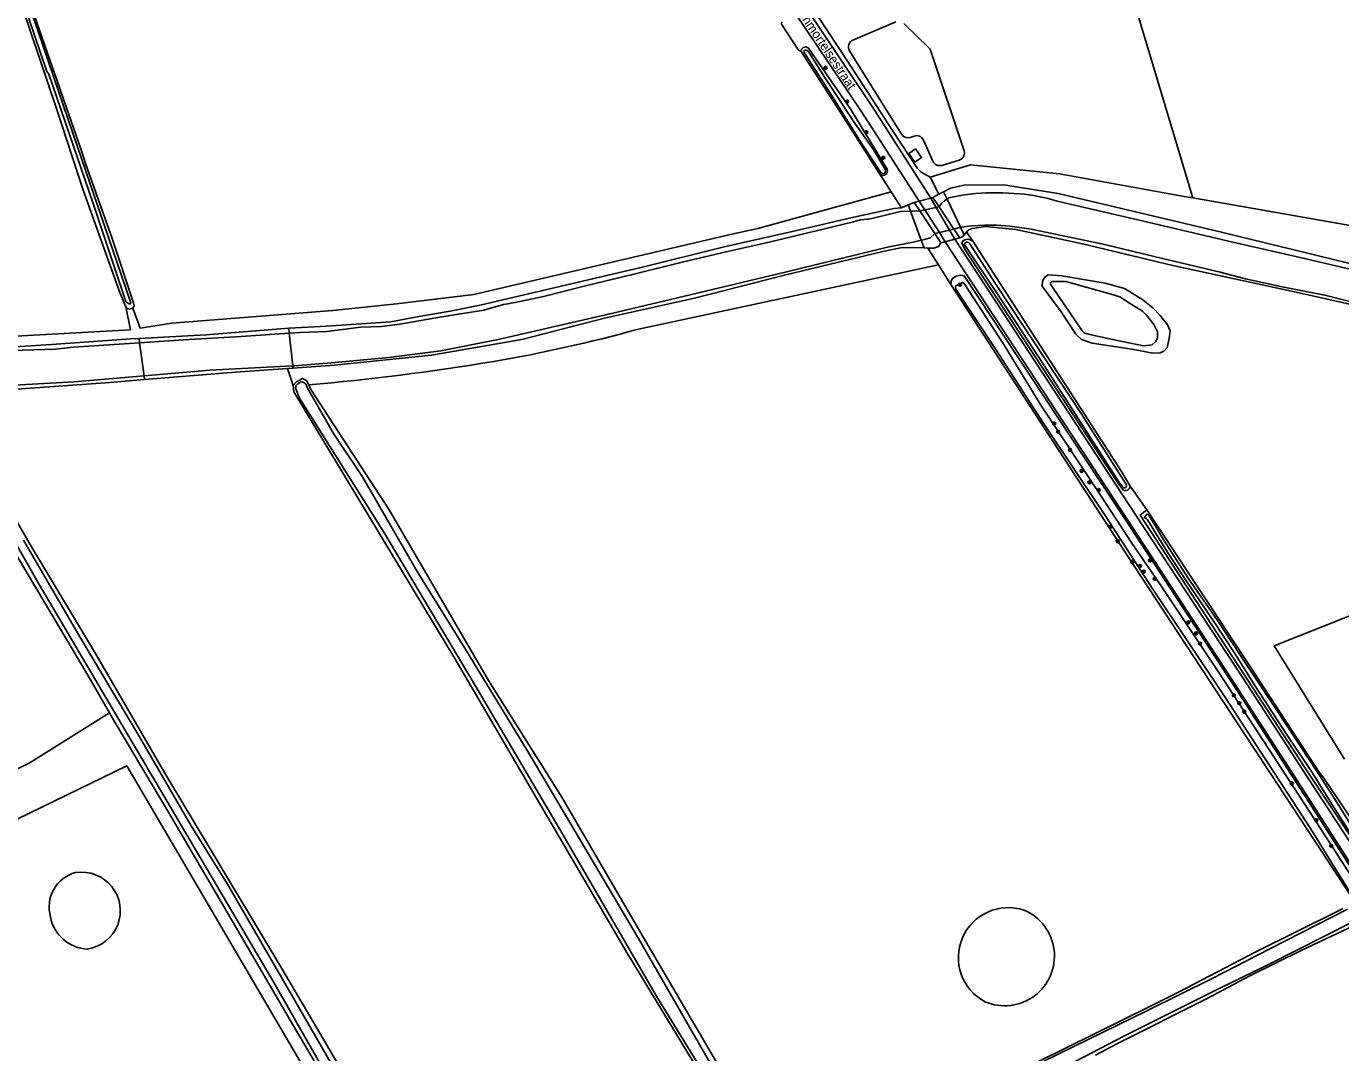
# Model space of a CAD drawing. Extents: x 140000 to 143000, y 403500 to 406000.
# Drawn here: x 140448.3 to 140803.5, y 405184.8 to 405462.4 of the extents above; entities that cross this region are included whole.
import ezdxf

# ---------------------------------------------------------------- set-up
doc = ezdxf.new("R2010")
doc.units = 0
for name, color, linetype in [('gg-afsc-erfafscheiding', 7, 'Continuous'), ('gg-anno-openbare ruimte label', 7, 'Continuous'), ('gg-bbg-bassin', 7, 'Continuous'), ('gg-bbg-bijgebouw', 7, 'Continuous'), ('gg-knt-bronhoudergrens', 7, 'Continuous'), ('gg-knt-verharding', 7, 'Continuous'), ('gg-kntw-bovenkant insteek waterloop', 7, 'Continuous'), ('gg-kntw-waterlijn', 7, 'Continuous'), ('gg-kwrk-kunstwerk niveau 01', 7, 'Continuous'), ('gt-grn-groengrens', 7, 'Continuous'), ('gt-grn-vlakafsluiter', 7, 'Continuous'), ('gt-symb-boom', 7, 'Continuous')]:
    doc.layers.add(name, color=color, linetype=linetype)

# ---------------------------------------------------------------- blocks, each defined once
blk = doc.blocks.new('gt0-BOOM')
at = {"layer": 'gt-symb-boom'}
for radius in [0.4, 0.2]:
    blk.add_circle((0, 0), radius, dxfattribs=at)

msp = doc.modelspace()

# ---------------------------------------------------------------- linework, layer by layer
at = {"layer": 'gg-afsc-erfafscheiding'}
for p, q in [((140704.06, 405404.23), (140702.41, 405406.81)), ((140751.14, 405331.61), (140746.6, 405337.98))]:
    msp.add_line(p, q, dxfattribs=at)
at = {"layer": 'gg-bbg-bassin'}
msp.add_lwpolyline([(140858.33, 405323.73), (140785.53, 405294.82), (140804.51, 405264.23)], dxfattribs=at)
at = {"layer": 'gg-bbg-bijgebouw'}
msp.add_lwpolyline([(140688.54, 405429.2), (140686.77, 405427.94), (140688.44, 405425.6), (140690.21, 405426.86), (140688.54, 405429.2)], dxfattribs=at)
at = {"layer": 'gg-knt-bronhoudergrens'}
for p, q in [((140684.24, 405680.52), (140763.52, 405415.94)), ((140763.52, 405415.94), (140806.03, 405408.46)), ((140694.78, 405397.86), (140613.7, 405380.47)), ((140698.12, 405392.53), (140694.78, 405397.86))]:
    msp.add_line(p, q, dxfattribs=at)
for points in [[(140604.3, 405559.42), (140607.77, 405550.91), (140610.79, 405543.85), (140617.24, 405532.9), (140631.12, 405511.58), (140643.29, 405494.3), (140653.59, 405478.15), (140670.4, 405452.64), (140682.39, 405434.2), (140689.15, 405423.92), (140690.15, 405422.91), (140692.57, 405421.54)], [(140727.49, 405422.46), (140703.41, 405424.92), (140692.57, 405421.54)], [(140727.49, 405422.46), (140761.19, 405416.36), (140763.52, 405415.94)]]:
    msp.add_lwpolyline(points, dxfattribs=at)
for centre, radius, start, end in [((140505.15, 405774.65), 408.86, 279.7046, 285.3952), ((140469.01, 406004.48), 641.49, 274.97336, 279.42638)]:
    msp.add_arc(centre, radius, start, end, dxfattribs=at)
at = {"layer": 'gg-knt-verharding'}
for points in [[(140689.6, 405415.1), (140673.87, 405439.38), (140644.21, 405483.71), (140613.35, 405531.74), (140610.71, 405535.83), (140608.28, 405540.05)], [(140692.73, 405415.93), (140676.87, 405440.7), (140646.95, 405485.52), (140615.72, 405533)], [(140696.62, 405404.11), (140745.76, 405329.12), (140774.82, 405284.61), (140792.12, 405257.91), (140813.06, 405225.13), (140823.04, 405212.19), (140836.71, 405190.58), (140867.36, 405142.18)], [(140699.22, 405404.8), (140748.14, 405330.13), (140777.2, 405285.95), (140794.6, 405259.12), (140815.83, 405226.84), (140825.12, 405214.08), (140838.86, 405192.54), (140843.51, 405185.44)]]:
    msp.add_lwpolyline(points, dxfattribs=at)
at = {"layer": 'gg-kntw-bovenkant insteek waterloop'}
for p, q in [((140683.3, 405463.54), (140671.69, 405458.64)), ((140692.27, 405456.48), (140685.47, 405463.12)), ((140670.77, 405455.74), (140684.82, 405433.17)), ((140701.71, 405428.72), (140692.77, 405455.68)), ((140687.14, 405432.33), (140688.25, 405432.7)), ((140690.71, 405431.61), (140693.28, 405425.86)), ((140695.68, 405424.76), (140700.39, 405426.18)), ((140693.31, 405416.09), (140694.92, 405416.96)), ((140696.15, 405417.62), (140694.92, 405416.96)), ((140686.62, 405414.05), (140684.77, 405413.27)), ((140688.26, 405414.74), (140686.62, 405414.05)), ((140691.94, 405402.39), (140690.93, 405402.42)), ((140518.86, 405369.82), (140520.33, 405369.92))]:
    msp.add_line(p, q, dxfattribs=at)
for points in [[(140434.63, 405503.84), (140435.74, 405500.7), (140437.75, 405495.19), (140456.44, 405440.13), (140463.54, 405418.31), (140473.57, 405390.41), (140475.19, 405386.47)], [(140437.18, 405504.25), (140436.96, 405503.92), (140436.86, 405503.63), (140436.94, 405503.13), (140440.21, 405494.79), (140445.32, 405480.03), (140463.32, 405428.4), (140464.29, 405425.29), (140471.49, 405404.96), (140477.27, 405387.63), (140477.43, 405386.8), (140477.1, 405386.15)], [(140680.9, 405423.73), (140671.07, 405439.88), (140659.7, 405456.45), (140658.98, 405456.78), (140658.26, 405456.64), (140657.79, 405456.14), (140657.67, 405455.52)], [(140678.99, 405422.42), (140668.47, 405438.79), (140657.67, 405455.52)], [(141018.51, 405360.64), (141009.64, 405362), (140996.04, 405364.24), (140967.09, 405369.25), (140954.81, 405371.43), (140914.38, 405378.37), (140880.22, 405384.58), (140812.67, 405396.62), (140771.61, 405406.64), (140727.14, 405417.18), (140712.33, 405419.46), (140701.72, 405419.41), (140698.04, 405418.63), (140696.15, 405417.62)], [(140519.21, 405380.74), (140519.28, 405380.74), (140529.44, 405381.25), (140546.78, 405382.49), (140554.39, 405383.91), (140562.8, 405385.31), (140571.28, 405387.05), (140615.56, 405397.42), (140636.47, 405402.62), (140656.02, 405407.06), (140671.88, 405410.79), (140682.69, 405413.09), (140684.77, 405413.27)], [(140701.77, 405405.96), (140701.39, 405405.53), (140700.54, 405405.15)], [(140701.77, 405405.96), (140701.88, 405406.09), (140702.25, 405406.67), (140702.41, 405406.81)], [(141018.51, 405349.3), (141017.59, 405349.36), (140948.25, 405361.12), (140924.45, 405365.53), (140907.21, 405369.19), (140879.74, 405373.39), (140863.88, 405376.62), (140829.27, 405382.93), (140811.08, 405386.03), (140792.24, 405390.32), (140758.11, 405397.69), (140733.73, 405403.53), (140715.68, 405407.43), (140707.53, 405408.19), (140703.91, 405407.73), (140702.97, 405407.33), (140702.41, 405406.81)], [(140520.33, 405369.92), (140531.52, 405370.69), (140557.79, 405373.43), (140582.21, 405377.69), (140604.55, 405383.4), (140628.85, 405388.88), (140653.15, 405395.09), (140679.77, 405401.5), (140684.99, 405402.56), (140690.93, 405402.42)], [(140695.47, 405403.81), (140694.79, 405402.79), (140693.51, 405402.36), (140691.94, 405402.39)], [(140704.06, 405404.23), (140703.17, 405404.73), (140702.74, 405404.83), (140701.93, 405404.64), (140701.48, 405404.38), (140701.14, 405403.82), (140702.01, 405401.89), (140743.63, 405338.41), (140744.11, 405337.84), (140744.68, 405336.96)], [(140746.6, 405337.98), (140744.24, 405342.02), (140704.06, 405404.23)], [(140810.71, 405225.92), (140810.92, 405226.22), (140810.96, 405226.69), (140807.82, 405232.33), (140791.76, 405257.54), (140774.46, 405284.37), (140745.49, 405328.61), (140701.75, 405394.86), (140700.87, 405395.04), (140699.62, 405394.77), (140698.6, 405394.19), (140698.19, 405393.5), (140698.12, 405392.53)], [(140739.8, 405392.9), (140728.15, 405394.9), (140724.43, 405395.16), (140723.44, 405394.49), (140722.87, 405393.38), (140722.81, 405392.14), (140727.97, 405385.14), (140731.91, 405379.09), (140733.41, 405377.67), (140736.3, 405376.71), (140747.09, 405375.1), (140752.7, 405374.01), (140754.67, 405374.04), (140755.67, 405374.5), (140756.64, 405375.48), (140757.14, 405377.93), (140757.44, 405380.04), (140756.7, 405381.61), (140754.69, 405384.16), (140752.82, 405386.16), (140750.05, 405388.42), (140745.05, 405391.46), (140739.8, 405392.9)], [(140806.8, 405226.39), (140747.41, 405316.85), (140698.12, 405392.53)], [(140477.1, 405386.15), (140476.18, 405385.88), (140475.55, 405386.06), (140475.19, 405386.47)], [(140478.73, 405377.94), (140496.9, 405378.93), (140519.21, 405380.74)], [(140478.73, 405377.94), (140476.55, 405377.82), (140455.12, 405376.31), (140437.85, 405375.22), (140433.08, 405374.62), (140426.24, 405373.94), (140420.3, 405372.76)], [(140518.86, 405369.82), (140504.77, 405368.85), (140480.22, 405366.82)], [(140480.22, 405366.82), (140470.87, 405366.04), (140441.85, 405364), (140434.9, 405363.88), (140427.45, 405363.09), (140424.63, 405362.44), (140424.16, 405362.33), (140423.32, 405362.03)], [(140524.62, 405365.4), (140524.04, 405366.62), (140522.92, 405367.11), (140521.3, 405366.19), (140520.38, 405365.21)], [(140623.34, 405126), (140634.61, 405132.65), (140651.46, 405142.23), (140651.76, 405142.96), (140651.27, 405144.79), (140610.59, 405211.92), (140564.04, 405291.41), (140520.54, 405363.5), (140520.38, 405365.21)], [(140524.62, 405365.4), (140525.21, 405364.17), (140546.33, 405331.63), (140573.16, 405285.5), (140593, 405253.88), (140612.94, 405219.65), (140654.65, 405148.38), (140655.09, 405147.89), (140656.13, 405147.47), (140656.73, 405147.31), (140657.86, 405147.71), (140671.69, 405155.23), (140694.51, 405167.85), (140721.46, 405182.24), (140752.32, 405197.51), (140759.65, 405201.21), (140780.54, 405212.09), (140802.92, 405223.18), (140804.07, 405223.8)], [(140610.52, 405047.27), (140594.37, 405075.45), (140567.19, 405121.86), (140537.74, 405172.8), (140516.53, 405208.9), (140485.69, 405260.4), (140466.95, 405292.77), (140449.91, 405321.13), (140428.29, 405358.27), (140427.65, 405359.01), (140426.71, 405359.25), (140425.74, 405359.04)], [(140470.77, 405276.7), (140464.65, 405287.38), (140447.29, 405316.5), (140431.05, 405343.94), (140424.12, 405357.16)], [(140751.14, 405331.61), (140749.28, 405330.18), (140794.95, 405260.14), (140820.16, 405222.27), (140833.58, 405202.92), (140836.04, 405204.42)], [(140751.14, 405331.61), (140753.94, 405327.36), (140754.61, 405326.34), (140780.06, 405287.68), (140797.71, 405260.66), (140798.97, 405259.02), (140822.35, 405224.33), (140836.04, 405204.42)], [(140640.8, 404987.56), (140631.03, 405003.93), (140617.98, 405027.46), (140610.69, 405039.45), (140607.4, 405044.62), (140583.24, 405086.18), (140563.04, 405119.59), (140539.25, 405160.24), (140519.56, 405193.61), (140504.21, 405219.99), (140487.3, 405248.8), (140472.2, 405274.2), (140470.77, 405276.7)], [(140808.48, 405220.55), (140808.07, 405219.95), (140807.3, 405219.32), (140792.81, 405212.41), (140778.9, 405205.59), (140767.23, 405199.4), (140743.19, 405187.32), (140737.27, 405184.18)]]:
    msp.add_lwpolyline(points, dxfattribs=at)
for centre, radius, start, end in [((140672.47, 405456.79), 2, 112.868, 211.9297), ((140690.87, 405455.06), 1.99, 18.3198, 45.6909), ((140686.51, 405434.23), 2, 211.8933, 288.3818), ((140688.88, 405430.8), 2, 24.0674, 108.3633), ((140699.81, 405428.09), 2, 286.713, 18.3878), ((140679.84, 405423.22), 1.17, 223.1443, 25.8191), ((140695.11, 405426.68), 2, 204.1677, 286.6822), ((140745.31, 405338.09), 1.29, 240.7405, 355.3549), ((140464, 405224.26), 9.57, 104.6246, 196.3387), ((140463.2, 405223.18), 10.47, 278.8153, 98.9126), ((140465.3, 405223.48), 10.66, 190.3624, 267.3795), ((140713.67, 405210.55), 13.5, 71.5425, 242.1739), ((140712.68, 405210.97), 13.46, 246.7492, 66.9671)]:
    msp.add_arc(centre, radius, start, end, dxfattribs=at)
at = {"layer": 'gg-kntw-waterlijn'}
for p, q in [((140689.76, 405412.47), (140691.1, 405412.75)), ((140694.2, 405413.41), (140691.1, 405412.75)), ((140694.97, 405413.57), (140694.2, 405413.41)), ((140693.83, 405406.3), (140695.04, 405406.6)), ((140697.78, 405407.27), (140695.04, 405406.6)), ((140698.95, 405407.55), (140697.78, 405407.27)), ((140700.78, 405408.01), (140698.95, 405407.55))]:
    msp.add_line(p, q, dxfattribs=at)
for points in [[(140435.78, 405503.26), (140435.77, 405502.7), (140439.57, 405492.04), (140447.34, 405469.27), (140453.83, 405450.12), (140454.34, 405449.44), (140466.3, 405414.47), (140475.19, 405387.97), (140475.69, 405387.49), (140476.08, 405387.28), (140476.38, 405387.31), (140476.55, 405387.55), (140457.02, 405444.57), (140447.24, 405473.5), (140440.36, 405493.33), (140436.46, 405503.33), (140436.18, 405503.54), (140436.07, 405503.49), (140435.91, 405503.43), (140435.78, 405503.26)], [(140680.46, 405423.57), (140677.15, 405429.13), (140671.78, 405436.84), (140663.12, 405450.09), (140659.65, 405455.55), (140659.03, 405455.92), (140658.69, 405455.88), (140658.49, 405455.68), (140658.45, 405455.45), (140659.12, 405454.3), (140664.84, 405445.44), (140674.48, 405430), (140679.04, 405423.12), (140679.27, 405422.73)], [(140704.81, 405417.14), (140701.19, 405416.69), (140697.62, 405415.97), (140697.11, 405415.63)], [(140687.25, 405412.35), (140687.96, 405412.37), (140689.76, 405412.47)], [(140697.11, 405415.63), (140696.63, 405415.33), (140695.65, 405414.48), (140694.97, 405413.57)], [(141018.51, 405359.64), (140998.36, 405362.91), (140961.55, 405369.5), (140909.64, 405378.29), (140878.33, 405384), (140846.31, 405389.5), (140824.51, 405393.34), (140809.08, 405395.99), (140793.72, 405399.6), (140774.36, 405404.01), (140748.65, 405410.05), (140726.91, 405415.09)], [(140687.25, 405412.35), (140684.49, 405412.25), (140676.75, 405410.4), (140675.61, 405410.2), (140673.73, 405410.04), (140671.79, 405409.48), (140649.42, 405404.11), (140637.37, 405401.4), (140625.87, 405398.69), (140612.48, 405395.3), (140599.4, 405392.17), (140588.06, 405389.26), (140581.69, 405387.97), (140578.44, 405387.28), (140577.24, 405387.15), (140571.95, 405385.62), (140560.03, 405383.73), (140549.19, 405381.79), (140544.25, 405381.16), (140538.59, 405381.01), (140529.56, 405379.83), (140522.25, 405379.59), (140519.35, 405379.39)], [(140690.15, 405404.52), (140691.05, 405404.74), (140692.56, 405405.17), (140693.83, 405406.3)], [(140808.78, 405387.26), (140799.21, 405389.67), (140787.7, 405391.88), (140777.77, 405394.12), (140770.92, 405395.84), (140755.37, 405399.6), (140739.3, 405403.44), (140719.85, 405407.49), (140714.09, 405408.28), (140710.47, 405408.57), (140707.29, 405408.57), (140703.68, 405408.43), (140700.94, 405408.05), (140700.78, 405408.01)], [(140520.27, 405370.56), (140520.78, 405370.59), (140531.78, 405371.46), (140546.24, 405372.8), (140560.3, 405374.62), (140575.77, 405377.67), (140606.76, 405384.79), (140627.65, 405389.71), (140653.38, 405395.85), (140681.02, 405402.66), (140687.93, 405403.99), (140690.15, 405404.52)], [(140744.71, 405337.69), (140744.12, 405338.48), (140743.56, 405339.2), (140723.39, 405370.64), (140710.28, 405390.62), (140702.06, 405402.88), (140701.78, 405403.39), (140701.92, 405403.67), (140702.37, 405403.97), (140702.78, 405403.96), (140703.28, 405403.52), (140710.56, 405392.15), (140733.52, 405357.35), (140744.16, 405340.63), (140745.59, 405338.33)], [(140770.6, 405287.61), (140754.68, 405311.43), (140746.86, 405322.9), (140738.77, 405335.3), (140722.48, 405359.95), (140712.45, 405376.31), (140701.76, 405392.86), (140701.29, 405393.11), (140699.52, 405392.23), (140699.35, 405391.84), (140699.53, 405391.31), (140710.26, 405374.95), (140723.07, 405355.12), (140739.88, 405330.1), (140752.53, 405310.44), (140772.15, 405281.05), (140795.3, 405245.47), (140806.57, 405227.28)], [(140725.11, 405393.05), (140725.11, 405392.64), (140725.6, 405391.79), (140733.66, 405379.99), (140734.2, 405379.48), (140735.28, 405379.13), (140744.01, 405377.23), (140750.31, 405375.94), (140752.52, 405376.24), (140753.53, 405377.11), (140753.99, 405378.16), (140753.96, 405379.79), (140752.97, 405381.71), (140750.98, 405384.21), (140749.89, 405385.37), (140746.85, 405387.23), (140743.79, 405389.23), (140742.09, 405389.76), (140729.22, 405393.39), (140725.53, 405393.34), (140725.11, 405393.05)], [(140478.89, 405376.77), (140490.74, 405377.55), (140506.36, 405378.49), (140519.35, 405379.39)], [(140478.89, 405376.77), (140461.01, 405375.59), (140456.16, 405375.09), (140447.16, 405374.79), (140435.5, 405373.96), (140427.26, 405372.93), (140421.71, 405371.78), (140420.64, 405371.57)], [(140480.08, 405367.84), (140497.83, 405369.35), (140520.27, 405370.56)], [(140423.04, 405363.03), (140427.7, 405363.98), (140433.75, 405364.76), (140446.63, 405365.41), (140461.22, 405366.23), (140480.08, 405367.84)], [(140639.48, 405170.86), (140613.68, 405215.66), (140600.4, 405238.24), (140583.78, 405266.3), (140567.02, 405293.79), (140553.94, 405314.91), (140539.13, 405340.51), (140531.27, 405352.25), (140524.16, 405364.71), (140523.84, 405365.61), (140523.3, 405366.09), (140522.81, 405366.24), (140522.4, 405366.17), (140521.68, 405365.73), (140521.09, 405365.12), (140521.11, 405364.3), (140522.13, 405361.81), (140544.94, 405325.61), (140570.1, 405283.25), (140593.23, 405243.8), (140618.59, 405200.13), (140644.86, 405157.16)], [(140641.79, 404988.11), (140634.2, 405001.25), (140617.83, 405029.18), (140588.54, 405079.34), (140573.42, 405104.99), (140555.88, 405134.64), (140536.62, 405166.24), (140514.81, 405204.45), (140496.74, 405235.21), (140451.35, 405312.03), (140442.54, 405327.56)], [(140813.9, 405232), (140801.14, 405251.99), (140795.8, 405260.58), (140789.07, 405270.72), (140780.27, 405284.11), (140775.7, 405291.5), (140769.54, 405300.86), (140761.81, 405312.31), (140756.66, 405320.17), (140751.27, 405328.94), (140751.06, 405329.22), (140750.88, 405329.34), (140750.6, 405329.4), (140750.47, 405329.53), (140750.54, 405329.75), (140751.1, 405330.4), (140751.58, 405330.28), (140753.68, 405326.77), (140755.55, 405323.64), (140762.27, 405313.13)], [(140447.47, 405323.38), (140462.47, 405297.7), (140478.82, 405270.22), (140492.78, 405246.18), (140502.62, 405230.35), (140523.21, 405194.87), (140544.72, 405157.44), (140564.15, 405124.22), (140578.49, 405099.56), (140593.16, 405074.64), (140606.34, 405052.43), (140612.51, 405041.49), (140628.49, 405013.78), (140642.67, 404988.61)], [(140762.27, 405313.13), (140770.17, 405301.73), (140778.09, 405289.58), (140786.53, 405277.01), (140796.9, 405261.24), (140802.13, 405253.1), (140812.87, 405235.71)], [(140810.17, 405226.64), (140796.87, 405247.23), (140796.23, 405248.27), (140770.6, 405287.61)], [(140805.33, 405223.66), (140784.49, 405212.98), (140768.75, 405204.91), (140751.08, 405196.13), (140723.24, 405182.52)], [(140654.89, 405139.18), (140701.33, 405166.53), (140745.04, 405189.38), (140770.13, 405201.88), (140783.61, 405208.45), (140806.81, 405220.2)]]:
    msp.add_lwpolyline(points, dxfattribs=at)
for centre, radius, start, end in [((140679.76, 405423.3), 0.748, 228.9008, 21.3676), ((140710.25, 405343.05), 74.29, 85.036, 94.2015), ((140712.32, 405366.87), 50.38, 73.1649, 85.0329), ((140745.07, 405338.12), 0.559, 229.7235, 22.308)]:
    msp.add_arc(centre, radius, start, end, dxfattribs=at)
at = {"layer": 'gg-kwrk-kunstwerk niveau 01'}
for p, q in [((140693.31, 405416.09), (140692.73, 405415.93)), ((140694.97, 405413.57), (140693.31, 405416.09)), ((140689.6, 405415.1), (140688.26, 405414.74)), ((140688.26, 405414.74), (140689.76, 405412.47)), ((140692.73, 405415.93), (140689.6, 405415.1)), ((140689.6, 405415.1), (140691.1, 405412.75)), ((140689.76, 405412.47), (140693.83, 405406.3)), ((140695.04, 405406.6), (140691.1, 405412.75)), ((140692.73, 405415.93), (140694.2, 405413.41)), ((140694.2, 405413.41), (140697.78, 405407.27)), ((140698.95, 405407.55), (140694.97, 405413.57)), ((140693.83, 405406.3), (140695.47, 405403.81)), ((140696.62, 405404.11), (140695.04, 405406.6)), ((140699.22, 405404.8), (140697.78, 405407.27)), ((140700.54, 405405.15), (140698.95, 405407.55)), ((140695.47, 405403.81), (140696.62, 405404.11)), ((140699.22, 405404.8), (140696.62, 405404.11)), ((140699.22, 405404.8), (140700.54, 405405.15))]:
    msp.add_line(p, q, dxfattribs=at)
at = {"layer": 'gt-grn-groengrens'}
for p, q in [((140682.04, 405417.59), (140678.99, 405422.42)), ((140684.77, 405413.27), (140682.04, 405417.59)), ((140694.78, 405397.86), (140691.94, 405402.39)), ((140520.38, 405365.21), (140518.86, 405369.82))]:
    msp.add_line(p, q, dxfattribs=at)
for points in [[(140657.67, 405455.52), (140656.98, 405455.88), (140652.33, 405462.95), (140652.5, 405463.53)], [(140682.04, 405417.59), (140645.99, 405407.68), (140638.93, 405406.17), (140569.19, 405389.8), (140548.28, 405387.35), (140531.07, 405385.48), (140487.61, 405382.05), (140479.07, 405380.72), (140477.1, 405386.15)], [(140311.08, 405337.92), (140312.69, 405337.82), (140325.53, 405342.56), (140376.88, 405361.84), (140404.32, 405372.04), (140414.99, 405374.86), (140421.33, 405376.27), (140427.67, 405377.18), (140435.52, 405378.03), (140476.39, 405380.3), (140475.19, 405386.47)], [(140318.52, 405200.05), (140449.03, 405263.08), (140470.77, 405276.7)], [(140324.5, 405189.04), (140475.43, 405262.4), (140592.61, 405062.34), (140590.84, 405060.78), (140635.63, 404986.82), (140632.67, 404984.58)]]:
    msp.add_lwpolyline(points, dxfattribs=at)
at = {"layer": 'gt-grn-vlakafsluiter'}
for p, q in [((140692.57, 405421.54), (140694.92, 405416.96)), ((140697.11, 405415.63), (140696.15, 405417.62)), ((140687.25, 405412.35), (140686.62, 405414.05)), ((140697.11, 405415.63), (140700.78, 405408.01)), ((140687.25, 405412.35), (140690.15, 405404.52)), ((140700.78, 405408.01), (140701.77, 405405.96)), ((140690.15, 405404.52), (140690.93, 405402.42)), ((140519.35, 405379.39), (140519.21, 405380.74)), ((140478.89, 405376.77), (140478.73, 405377.94)), ((140519.35, 405379.39), (140520.27, 405370.56)), ((140478.89, 405376.77), (140480.08, 405367.84)), ((140520.27, 405370.56), (140520.33, 405369.92)), ((140480.08, 405367.84), (140480.22, 405366.82))]:
    msp.add_line(p, q, dxfattribs=at)

# ---------------------------------------------------------------- block references
at = {"layer": 'gt-symb-boom'}
for p in [(140664.27, 405451.11), (140670.12, 405442), (140675.3, 405433.74), (140679.88, 405426.83), (140700.62, 405392.47), (140726.09, 405354.93), (140727.14, 405352.78), (140730.34, 405347.81), (140733.46, 405342.14), (140735.58, 405339.05), (140738.11, 405337.02), (140741.2, 405326.99), (140743.26, 405323.1), (140747.16, 405317.52), (140749.25, 405316.43), (140751.92, 405317.93), (140750.25, 405314.93), (140753.24, 405312.97), (140762.35, 405301.23), (140764.4, 405298.21), (140765.5, 405295.45), (140774.62, 405281.43), (140776.11, 405279.33), (140777.44, 405277.04), (140790.24, 405257.62), (140796.9, 405247.66), (140800.94, 405240.77)]:
    msp.add_blockref('gt0-BOOM', p, dxfattribs=at)

# ---------------------------------------------------------------- texts
at = {"layer": 'gg-anno-openbare ruimte label'}
msp.add_text('Biezenmortelsestraat', height=2.5, rotation=303.7, dxfattribs=at).set_placement((140653.21, 405471.11))

doc.saveas('drawing.dxf')
